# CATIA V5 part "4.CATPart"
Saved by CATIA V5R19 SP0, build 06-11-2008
Part number: 3
Bounding box of the stored display mesh (mm): x -440 to 100, y 430.135 to 509.865, z -240 to -20
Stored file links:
  G:\EU_thinkMotion\CFAO_2010\MMS_groupe3\MMS_groupe3\A reprendre\bblot\BLOT\4.CATPart
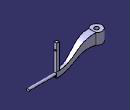
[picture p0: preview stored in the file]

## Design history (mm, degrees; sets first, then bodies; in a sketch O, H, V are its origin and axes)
Body1 (main body)
  DatumSurface1
  DatumCurve1
  DatumSurface2
  Sketch1 on face of DatumSurface1, origin (0, 0, -160), H (1, 0, 0), V (0, 1, 0)
    circle A1 centre (-400, 470) radius 15
    reference projected circle E1 centre (-400, 470) radius 15 from edge of DatumCurve1
    circle A2 centre (-400, 470) radius 40
    radius A2 = 40
    coincidence: A1 E1
    concentricity: A2 A1
  Pad1: profile Sketch1, direction (0, 0, 1), up to face of DatumSurface2
  DatumPoint1
  Plane1: type OffsetPt, RefPlane zx-plane, RefPoint DatumPoint1
  Line1: stored without definition
  Plane2 "Plan 9-10 droite": stored without definition
  Line2 "as (BF)": stored without definition
  Line3 "as (BF)": stored without definition
  Plane3 "Plan 9-10 droite": stored without definition
  Line4 to Line6 "as (BF)": stored without definition
  Sketch2 on Plane1, origin (0, 470, 0), H (-1, 0, 0), V (0, 0, 1)
    line L1 (370, -80) -> (370, -160)
    point P1 (370, -80)
    point P2 (370, -160)
    spline S1 through (370, -80) (255, -120) (195, -173) (100, -200)
    reference projected line E1 through (400, 0) direction (0, 1) from Line1
    reference projected line E2 (360, -80) -> (440, -80) from edge [face of Pad1 from Sketch1.A2 | end face of Pad1]
    reference intersected line E3 through (100, 0) direction (0, -1) from Plane2
    reference projected line E4 through (0, -220) direction (-1, 0) from Line2
    spline S2 through (370, -160) (255, -172) (195, -213) (100, -240)
    reference intersected line E5 through (100, 0) direction (0, -1) from Plane3
    reference projected line E6 through (0, -220) direction (-1, 0) from Line4
    reference projected line E7 (360, -160) -> (440, -160) from edge [start face of Pad1 | face of Pad1 from Sketch1.A2]
    reference projected line E8 through (0, -220) direction (-1, 0) from Line5
    reference projected line E9 through (0, -220) direction (-1, 0) from Line6
    construction line L2 (195, -173) -> (195, -213)
    point P3 (195, -213)
    point P4 (195, -173)
    axis line L3 (255, -120) -> (255, -172)
    point P5 (255, -172)
    point P6 (255, -120)
    line L4 (100, -240) -> (100, -200)
    point P7 (100, -240)
    point P8 (100, -200)
    point P9 (370, -80)
    point P10 (100, -200)
    point P11 (100, -240)
    point P12 (370, -160)
    point P13 (255, -120)
    point P14 (195, -173)
    point P15 (195, -213)
    point P16 (255, -172)
    distance E1 L1 = 30
    distance P10 E4 = 20
    distance P11 E6 = 20
    distance L1 P13 = 115
    distance E8 P13 = 100
    distance P14 E9 = 47
    distance L1 P14 = 175
    length L3 = 52
    length L2 = 40
    vertical: L1 V, L2 V, L3 V, L4 V
    coincidence: P9 P1, E2 P9, E3 P10, P11 E5, P12 P2, P12 E7, P15 P3, P4 S1, P16 P5, P6 S1, L3 P13, P14 P4, P11 P7, P10 P8
  DatumPoint2
  Plane4: type OffsetPt, RefPlane xy-plane, RefPoint DatumPoint2
  Sketch3 on Plane4, origin (0, 0, -220), H (1, 0, 0), V (0, 1, 0)
    line L1 (-370, 470) -> (-370, 496.4575)
    point P1 (-370, 470)
    point P2 (-370, 496.4575)
    spline S1 through (-370, 496.4575) (-305, 494) (-165, 481) (-100, 480)
    reference projected circle E1 centre (-400, 470) radius 40 from edge [face of Pad1 from Sketch1.A2 | end face of Pad1]
    reference projected point E2 (-370, 470) from vertex [element of Sketch2 | element of Sketch2]
    reference projected line E3 (-370, 470) -> (-100, 470) from Sketch2.S1
    line L2 (-100, 470) -> (-100, 480)
    point P3 (-100, 480)
    point P4 (-100, 470)
    reference projected point E4 (-100, 470) from vertex [element of Sketch2 | element of Sketch2]
    reference projected line E5 (-370, 470) -> (-100, 470) from Sketch2.S1
    reference projected line E6 (-370, 470) -> (-100, 470) from Sketch2.S1
    axis line L3 (-100, 470) -> (-370, 470)
    spline S2 through (-370, 443.5425) (-305, 446) (-165, 459) (-100, 460)
    point P5 (-370, 443.5425)
    point P6 (-370, 470)
    line L4 (-370, 470) -> (-370, 443.5425)
    point P7 (-100, 460)
    point P8 (-100, 470)
    line L5 (-100, 470) -> (-100, 460)
    point P9 (-370, 496.4575)
    point P10 (-100, 480)
    point P11 (-165, 481)
    point P12 (-305, 494)
    point P13 (-100, 460)
    point P14 (-370, 443.5425)
    point P15 (-165, 459)
    point P16 (-305, 446)
    distance P10 E3 = 10
    distance L2 P11 = 65
    distance L1 P12 = 65
    distance P12 E5 = 24
    distance E6 P11 = 11
    vertical: L1 V, L2 V
    coincidence: P9 P2, P9 E1, P1 E2, P10 P3, P4 E4, P1 P6, P4 P8, P14 P5, P13 P7
    horizontal: L3 H
    symmetry: S1 S2 L3, P2 P5 L3, P1 P6 L3, L1 L4 L3, P3 P7 L3, P4 P8 L3, L2 L5 L3, P10 P13 L3, P9 P14 L3, P11 P15 L3, P12 P16 L3
  SolidCombine1: FirstComponentProfile Sketch2, FirstComponentDirection Sketch2, SecondComponentProfile Sketch3, SecondComponentDirection Sketch3
  Line7: stored without definition
  Plane5 "Plan 9-10 gauche": stored without definition
  Sketch4 on face of SolidCombine1 from Sketch3.L5, origin (-100, 0, 0), H (0, 1, 0), V (0, 0, 1)
    circle A1 centre (470, -220) radius 10
    point P1 (470, -220)
    reference projected line E1 (460, -240) -> (460, -200) from edge [face of SolidCombine1 from Sketch3.L5 | face of SolidCombine1 from Sketch3.S2]
    reference projected line E2 (480, -240) -> (480, -200) from edge [face of SolidCombine1 from Sketch3.S1 | face of SolidCombine1 from Sketch3.L2]
    axis line L1 (470, -240) -> (470, -200)
    point P2 (470, -240)
    point P3 (470, -200)
    reference projected line E3 (460, -200) -> (470, -200) from edge [face of SolidCombine1 from Sketch3.L5 | face of SolidCombine1 from Sketch2.S1]
    reference projected line E4 (460, -240) -> (470, -240) from edge [face of SolidCombine1 from Sketch2.S2 | face of SolidCombine1 from Sketch3.L5]
    reference projected line E5 through (470, 0) direction (0, 1) from Line7
    tangency: A1 E1, A1 E2
    vertical: L1 V
    coincidence: P3 E3, P2 E4, L1 E5
    midpoint: P1 L1
  Pad2: profile Sketch4, direction (1, 0, 0), up to Plane5
  DatumSurface3
  Sketch5 on Plane4, origin (0, 0, -220), H (1, 0, 0), V (0, 1, 0)
    line L1 (-120, 479.7014) -> (-100, 479.7014)
    line L2 (-100, 479.7014) -> (-100, 460.2986)
    line L3 (-100, 460.2986) -> (-120, 460.2986)
    line L4 (-120, 460.2986) -> (-120, 479.7014)
    reference projected line E1 (-100, 470) -> (-100, 480) from edge [face of SolidCombine1 from Sketch3.L2 | face of SolidCombine1 from Sketch2.S1]
    reference projected curve E2 from edge [face of SolidCombine1 from Sketch3.S1 | face of SolidCombine1 from Sketch2.S1]
    reference projected curve E3 from edge [face of SolidCombine1 from Sketch2.S1 | face of SolidCombine1 from Sketch3.S2]
    reference intersected line E4 through (-120, 0) direction (0, -1) from face of DatumSurface3
    horizontal: L1 H, L3 H
    vertical: L2 V, L4 V
    coincidence: L2 E1, L4 E4
    tangency: L1 E2, L3 E3
  Pad3: profile Sketch5, direction (0, 0, 1), length 200
  Sketch6 on face of Pad3, origin (-100, 469.0731, -37.6428), H (0, 1, 0), V (0, 0, 1)
    point P1 (0.9269, -32.3572)
    reference projected point E1 (0.9269, -32.3572) from Line8
    coincidence: P1 E1
  Hole1: placed by Sketch6, at (-100, 470, -70) direction (-1, 0, 0), diameter 10, through (limit type 3)
  Line8: stored without definition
